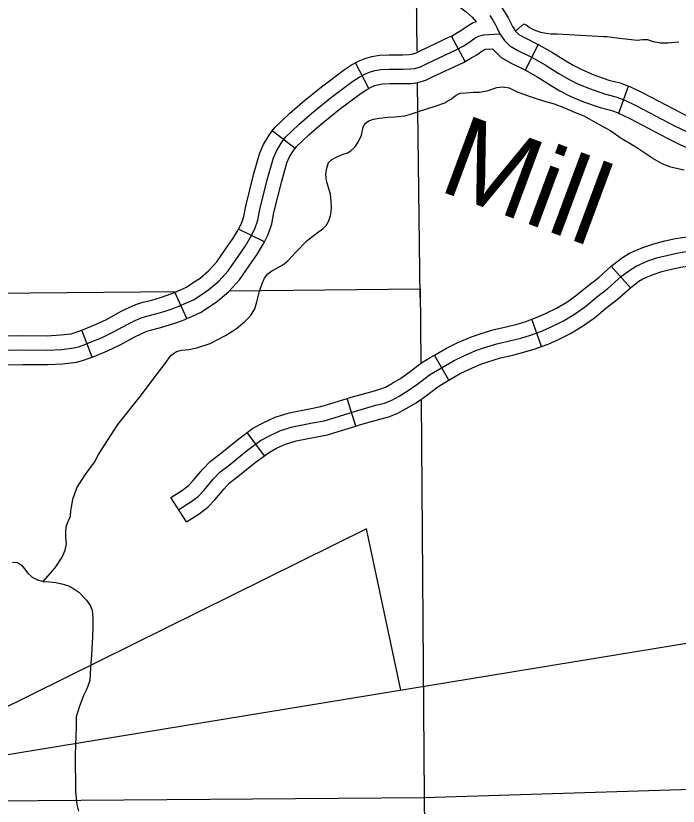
# Model space of a CAD drawing. Extents: x -3711 to 825, y -151 to 1050.
# Drawn here: x -2857.63 to -2819.08, y 378.25 to 424.26 of the extents above; entities that cross this region are included whole.
import ezdxf

# ---------------------------------------------------------------- set-up
doc = ezdxf.new("R2010")
doc.units = 0
for name, color, linetype in [('Level 32', 7, 'Continuous'), ('Level 35', 7, 'Continuous'), ('Level 46', 7, 'Continuous'), ('Level 5', 7, 'Continuous'), ('Level 8', 7, 'Continuous'), ('R_Dimension', 7, 'Continuous')]:
    doc.layers.add(name, color=color, linetype=linetype)

msp = doc.modelspace()

# ---------------------------------------------------------------- linework, layer by layer
at = {"layer": 'Level 32'}
for p, q in [((-2831.468, 421.611), (-2832.277, 423.084)), ((-2827.96, 421.091), (-2827.223, 422.602)), ((-2837.085, 420.034), (-2837.858, 421.527)), ((-2822.533, 418.595), (-2821.959, 420.175)), ((-2841.374, 416.53), (-2842.704, 417.558)), ((-2843.153, 411.098), (-2844.657, 411.85)), ((-2821.857, 408.431), (-2822.976, 409.685)), ((-2847.678, 406.635), (-2848.365, 408.17)), ((-2827.023, 405.018), (-2827.598, 406.598)), ((-2853.182, 404.399), (-2853.791, 405.965)), ((-2832.418, 403.056), (-2833.264, 404.509)), ((-2837.835, 400.379), (-2838.334, 401.984)), ((-2843.154, 398.657), (-2844.158, 400.006)), ((-2847.691, 394.81), (-2848.594, 396.228))]:
    msp.add_line(p, q, dxfattribs=at)
for points in [[(-2831.581, 426.503), (-2831.428, 426.451), (-2830.858, 426.182), (-2830.328, 425.784), (-2829.868, 425.355), (-2829.37, 424.794), (-2829.145, 424.433), (-2828.98, 424.149), (-2828.881, 423.958), (-2828.72, 423.633), (-2828.54, 423.369), (-2828.351, 423.18), (-2828.02, 422.991), (-2827.223, 422.602)], [(-2832.128, 424.913), (-2832.061, 424.891), (-2831.729, 424.734), (-2831.409, 424.494), (-2831.073, 424.18), (-2830.837, 423.914)], [(-2830.046, 424.289), (-2829.865, 424), (-2829.717, 423.744), (-2829.631, 423.578), (-2829.448, 423.208), (-2829.19, 422.83), (-2828.866, 422.507), (-2828.413, 422.247), (-2827.572, 421.837), (-2826.817, 421.405), (-2826.061, 420.93), (-2825.565, 420.628), (-2825.004, 420.347), (-2824.292, 420.045), (-2823.365, 419.721), (-2822.696, 419.548), (-2822.221, 419.376), (-2821.509, 419.03), (-2819.287, 417.864), (-2818.596, 417.519)], [(-2832.277, 423.084), (-2832.007, 423.232), (-2831.716, 423.403), (-2831.363, 423.662), (-2831.003, 423.871), (-2830.837, 423.914)], [(-2859.541, 404.788), (-2857.224, 404.812), (-2855.785, 404.8), (-2854.955, 404.847), (-2854.253, 404.929), (-2853.984, 404.999), (-2853.656, 405.116), (-2853.235, 405.28), (-2852.638, 405.526), (-2851.972, 405.842), (-2851.071, 406.333), (-2850.673, 406.521), (-2850.334, 406.673), (-2850.006, 406.778), (-2849.48, 406.907), (-2848.942, 407.071), (-2848.532, 407.212), (-2848.134, 407.352), (-2847.69, 407.551), (-2847.292, 407.738), (-2846.777, 408.066), (-2846.391, 408.324), (-2845.818, 408.815), (-2845.268, 409.412), (-2844.73, 410.197), (-2844.262, 410.864), (-2843.958, 411.368), (-2843.712, 411.859), (-2843.549, 412.374), (-2843.42, 413.007), (-2842.964, 414.856), (-2842.636, 415.992), (-2842.461, 416.39), (-2842.191, 416.847), (-2841.911, 417.21), (-2841.56, 417.549), (-2841.139, 417.947), (-2840.402, 418.591), (-2839.325, 419.469), (-2838.003, 420.452), (-2837.652, 420.687), (-2837.313, 420.862), (-2837.032, 420.991), (-2836.728, 421.073), (-2836.377, 421.131), (-2835.886, 421.155), (-2835.09, 421.155), (-2834.658, 421.167), (-2834.4, 421.202), (-2834.073, 421.295), (-2833.733, 421.459), (-2831.955, 422.302), (-2831.592, 422.501), (-2831.253, 422.7), (-2830.902, 422.958), (-2830.68, 423.087), (-2830.411, 423.157), (-2829.448, 423.208)], [(-2837.858, 421.527), (-2837.682, 421.618), (-2837.319, 421.784), (-2836.907, 421.895), (-2836.467, 421.969), (-2835.906, 421.995), (-2835.102, 421.995), (-2834.726, 422.006), (-2834.573, 422.026), (-2834.373, 422.084), (-2834.096, 422.217), (-2832.338, 423.051), (-2832.277, 423.084)], [(-2827.223, 422.603), (-2827.179, 422.581), (-2826.384, 422.126), (-2825.619, 421.645), (-2825.158, 421.364), (-2824.652, 421.111), (-2823.989, 420.83), (-2823.12, 420.526), (-2822.446, 420.352), (-2821.959, 420.175)], [(-2831.468, 421.611), (-2831.178, 421.77), (-2830.791, 421.997), (-2830.442, 422.253), (-2830.357, 422.302), (-2830.281, 422.322), (-2829.891, 422.342)], [(-2829.891, 422.342), (-2829.381, 421.833), (-2828.806, 421.504), (-2827.96, 421.091)], [(-2842.704, 417.558), (-2842.539, 417.772), (-2842.141, 418.157), (-2841.704, 418.569), (-2840.944, 419.233), (-2839.842, 420.132), (-2838.488, 421.14), (-2838.08, 421.412), (-2837.858, 421.527)], [(-2837.085, 420.034), (-2836.944, 420.106), (-2836.746, 420.198), (-2836.549, 420.251), (-2836.288, 420.294), (-2835.866, 420.314), (-2835.079, 420.314), (-2834.589, 420.327), (-2834.227, 420.377), (-2833.772, 420.507), (-2833.37, 420.701), (-2831.573, 421.553), (-2831.468, 421.611)], [(-2827.965, 421.094), (-2827.249, 420.684), (-2826.504, 420.216), (-2825.973, 419.892), (-2825.357, 419.584), (-2824.595, 419.261), (-2823.609, 418.916), (-2822.945, 418.745), (-2822.533, 418.595)], [(-2821.958, 420.175), (-2821.893, 420.151), (-2821.13, 419.781), (-2818.903, 418.612), (-2818.244, 418.283), (-2817.725, 418.063), (-2817.187, 417.863), (-2816.65, 417.704)], [(-2841.374, 416.53), (-2841.283, 416.647), (-2840.979, 416.941), (-2840.573, 417.325), (-2839.859, 417.949), (-2838.808, 418.806), (-2837.519, 419.765), (-2837.225, 419.961), (-2837.085, 420.034)], [(-2822.549, 418.601), (-2821.888, 418.28), (-2819.67, 417.116), (-2818.949, 416.755), (-2818.345, 416.5), (-2817.719, 416.267), (-2817.128, 416.092)], [(-2844.657, 411.85), (-2844.494, 412.176), (-2844.363, 412.586), (-2844.24, 413.191), (-2843.776, 415.074), (-2843.428, 416.279), (-2843.21, 416.774), (-2842.889, 417.319), (-2842.704, 417.558)], [(-2843.153, 411.098), (-2842.931, 411.542), (-2842.734, 412.163), (-2842.6, 412.822), (-2842.151, 414.639), (-2841.844, 415.705), (-2841.711, 416.006), (-2841.494, 416.374), (-2841.374, 416.53)], [(-2848.365, 408.17), (-2848.041, 408.315), (-2847.699, 408.476), (-2847.236, 408.77), (-2846.9, 408.995), (-2846.403, 409.421), (-2845.927, 409.938), (-2845.421, 410.676), (-2844.967, 411.323), (-2844.695, 411.773), (-2844.657, 411.85)], [(-2822.976, 409.685), (-2822.907, 409.747), (-2822.31, 410.201), (-2821.903, 410.445), (-2821.135, 410.782), (-2820.491, 410.996), (-2819.851, 411.157), (-2819.233, 411.294), (-2818.416, 411.414), (-2817.906, 411.414), (-2817.393, 411.414), (-2816.907, 411.414), (-2816.766, 411.402)], [(-2847.678, 406.635), (-2847.339, 406.787), (-2846.886, 407.001), (-2846.318, 407.362), (-2845.883, 407.653), (-2845.233, 408.21), (-2844.609, 408.887), (-2844.039, 409.718), (-2843.557, 410.405), (-2843.221, 410.962), (-2843.153, 411.098)], [(-2848.142, 395.519), (-2847.437, 395.968), (-2847.01, 396.289), (-2846.668, 396.652), (-2846.134, 397.294), (-2845.749, 397.7), (-2845.215, 398.107), (-2844.211, 398.919), (-2843.377, 399.539), (-2842.822, 399.839), (-2842.223, 400.117), (-2841.518, 400.33), (-2840.364, 400.566), (-2839.68, 400.694), (-2839.103, 400.865), (-2837.864, 401.25), (-2836.667, 401.592), (-2836.176, 401.72), (-2835.748, 401.892), (-2835.321, 402.127), (-2834.787, 402.448), (-2834.231, 402.832), (-2833.547, 403.367), (-2833.077, 403.645), (-2832.159, 404.18), (-2831.582, 404.458), (-2830.855, 404.778), (-2830.406, 404.928), (-2829.637, 405.163), (-2828.889, 405.334), (-2828.227, 405.506), (-2827.671, 405.677), (-2826.966, 405.933), (-2826.432, 406.168), (-2825.748, 406.511), (-2825.107, 406.896), (-2824.466, 407.345), (-2823.825, 407.879), (-2823.162, 408.392), (-2822.372, 409.098), (-2821.837, 409.504), (-2821.517, 409.697), (-2820.833, 409.996), (-2820.256, 410.189), (-2819.658, 410.338), (-2819.081, 410.467), (-2818.354, 410.574)], [(-2827.598, 406.598), (-2827.279, 406.714), (-2826.789, 406.929), (-2826.153, 407.248), (-2825.565, 407.601), (-2824.977, 408.013), (-2824.351, 408.534), (-2823.7, 409.039), (-2822.976, 409.685)], [(-2821.857, 408.431), (-2821.836, 408.449), (-2821.365, 408.807), (-2821.13, 408.948), (-2820.531, 409.211), (-2820.021, 409.381), (-2819.465, 409.52), (-2818.928, 409.64), (-2818.293, 409.733), (-2817.906, 409.733), (-2817.393, 409.733), (-2816.98, 409.733), (-2816.912, 409.727)], [(-2853.791, 405.965), (-2853.548, 406.06), (-2852.979, 406.295), (-2852.353, 406.591), (-2851.452, 407.083), (-2851.024, 407.285), (-2850.635, 407.459), (-2850.235, 407.588), (-2849.702, 407.718), (-2849.201, 407.871), (-2848.809, 408.005), (-2848.447, 408.133), (-2848.365, 408.17)], [(-2827.023, 405.018), (-2826.652, 405.153), (-2826.074, 405.407), (-2825.343, 405.773), (-2824.649, 406.19), (-2823.955, 406.676), (-2823.298, 407.224), (-2822.624, 407.746), (-2821.857, 408.431)], [(-2853.182, 404.399), (-2852.922, 404.499), (-2852.298, 404.757), (-2851.59, 405.092), (-2850.69, 405.584), (-2850.322, 405.757), (-2850.032, 405.887), (-2849.777, 405.969), (-2849.257, 406.096), (-2848.683, 406.271), (-2848.256, 406.418), (-2847.822, 406.571), (-2847.678, 406.635)], [(-2833.264, 404.509), (-2832.553, 404.923), (-2831.934, 405.221), (-2831.158, 405.563), (-2830.662, 405.729), (-2829.854, 405.976), (-2829.088, 406.151), (-2828.456, 406.315), (-2827.939, 406.474), (-2827.598, 406.598)], [(-2859.272, 405.632), (-2857.225, 405.652), (-2855.806, 405.641), (-2855.027, 405.685), (-2854.408, 405.757), (-2854.232, 405.803), (-2853.95, 405.904), (-2853.791, 405.965)], [(-2832.418, 403.056), (-2831.764, 403.437), (-2831.229, 403.694), (-2830.552, 403.994), (-2830.15, 404.127), (-2829.42, 404.351), (-2828.69, 404.518), (-2827.998, 404.696), (-2827.403, 404.879), (-2827.023, 405.018)], [(-2838.334, 401.984), (-2838.104, 402.056), (-2836.889, 402.403), (-2836.439, 402.521), (-2836.109, 402.653), (-2835.74, 402.856), (-2835.243, 403.154), (-2834.73, 403.51), (-2834.022, 404.063), (-2833.503, 404.37), (-2833.264, 404.509)], [(-2859.348, 403.949), (-2857.223, 403.971), (-2855.765, 403.959), (-2854.882, 404.009), (-2854.097, 404.1), (-2853.736, 404.195), (-2853.362, 404.328), (-2853.182, 404.399)], [(-2837.835, 400.379), (-2837.624, 400.444), (-2836.446, 400.781), (-2835.912, 400.92), (-2835.388, 401.13), (-2834.902, 401.398), (-2834.331, 401.741), (-2833.733, 402.155), (-2833.073, 402.671), (-2832.652, 402.92), (-2832.418, 403.056)], [(-2844.158, 400.006), (-2843.83, 400.25), (-2843.198, 400.59), (-2842.524, 400.904), (-2841.724, 401.146), (-2840.526, 401.391), (-2839.878, 401.512), (-2839.348, 401.669), (-2838.334, 401.984)], [(-2843.154, 398.657), (-2842.924, 398.828), (-2842.445, 399.087), (-2841.923, 399.329), (-2841.312, 399.515), (-2840.203, 399.741), (-2839.483, 399.876), (-2838.859, 400.061), (-2837.835, 400.379)], [(-2848.594, 396.228), (-2847.916, 396.66), (-2847.572, 396.918), (-2847.298, 397.21), (-2846.763, 397.852), (-2846.312, 398.328), (-2845.734, 398.768), (-2844.726, 399.583), (-2844.158, 400.006)], [(-2847.691, 394.81), (-2846.958, 395.276), (-2846.447, 395.66), (-2846.038, 396.095), (-2845.505, 396.735), (-2845.186, 397.073), (-2844.696, 397.445), (-2843.695, 398.255), (-2843.154, 398.657)]]:
    msp.add_lwpolyline(points, dxfattribs=at)
at = {"layer": 'Level 35'}
for points in [[(-2832.325, 419.393), (-2831.994, 419.649), (-2831.767, 419.763), (-2831.439, 419.788), (-2831.009, 419.813), (-2830.643, 419.826), (-2830.201, 419.902), (-2829.621, 420.091), (-2829.28, 420.129), (-2828.913, 420.066), (-2828.408, 419.826), (-2827.638, 419.548), (-2826.805, 419.283), (-2826.3, 419.131), (-2825.694, 418.903), (-2825.062, 418.638), (-2824.57, 418.449), (-2823.812, 418.019), (-2822.991, 417.564), (-2822.385, 417.147)], [(-2840.662, 411.174), (-2840.001, 411.681), (-2839.764, 411.863), (-2839.568, 412.058), (-2839.4, 412.324), (-2839.313, 412.633), (-2839.275, 412.874), (-2839.262, 413.088), (-2839.275, 413.48), (-2839.313, 413.884), (-2839.452, 414.327), (-2839.553, 414.655), (-2839.591, 415.047), (-2839.527, 415.401), (-2839.426, 415.717), (-2839.262, 415.881), (-2838.972, 416.033), (-2838.568, 416.209), (-2838.328, 416.285), (-2838.126, 416.412), (-2837.899, 416.626), (-2837.709, 416.917), (-2837.507, 417.321), (-2837.406, 417.776), (-2837.267, 418.016), (-2837.078, 418.143), (-2836.813, 418.244), (-2836.472, 418.307), (-2835.979, 418.358), (-2835.575, 418.383), (-2834.994, 418.433), (-2834.704, 418.522), (-2834.123, 418.711), (-2833.214, 419.002), (-2832.658, 419.204), (-2832.431, 419.343), (-2832.325, 419.393)], [(-2822.385, 417.147), (-2821.59, 416.667), (-2820.428, 415.896), (-2820.037, 415.669), (-2819.519, 415.466), (-2818.724, 415.302)], [(-2850.301, 402.197), (-2849.571, 403.196), (-2848.924, 404.033), (-2848.605, 404.48), (-2848.265, 404.714), (-2847.989, 404.799), (-2847.564, 404.841), (-2847.097, 404.926), (-2846.311, 405.181), (-2845.418, 405.649), (-2844.781, 406.053), (-2844.313, 406.457), (-2843.973, 406.797), (-2843.718, 407.201), (-2843.591, 407.605), (-2843.442, 408.243), (-2843.293, 408.69), (-2843.145, 408.987), (-2842.954, 409.243), (-2842.72, 409.413), (-2842.401, 409.583), (-2842.082, 409.774), (-2841.785, 410.008), (-2841.353, 410.482), (-2840.662, 411.174)], [(-2856.03, 391.342), (-2855.328, 392.135), (-2854.925, 392.752), (-2854.755, 393.156), (-2854.67, 393.518), (-2854.712, 393.879), (-2854.712, 394.198), (-2854.691, 394.538), (-2854.585, 394.836), (-2854.436, 395.134), (-2854.415, 395.453), (-2854.372, 395.75), (-2854.309, 396.133), (-2854.075, 396.792), (-2853.586, 397.536), (-2853.055, 398.281), (-2852.821, 398.727), (-2851.683, 400.467), (-2850.301, 402.197)], [(-2857.819, 392.464), (-2857.531, 392.434), (-2857.303, 392.282), (-2857.122, 392.07), (-2856.924, 391.827), (-2856.682, 391.584), (-2856.364, 391.433), (-2856.03, 391.342), (-2855.666, 391.311), (-2855.287, 391.266), (-2854.878, 391.175), (-2854.56, 391.084), (-2854.363, 390.978), (-2853.953, 390.705), (-2853.514, 390.249), (-2853.302, 389.946), (-2853.18, 389.673), (-2853.15, 389.188), (-2853.15, 388.657), (-2853.165, 388.126), (-2853.211, 387.064), (-2853.271, 386.305), (-2853.317, 385.562), (-2853.484, 385.092), (-2853.681, 384.697), (-2853.938, 384.015), (-2854.12, 383.453), (-2854.12, 383.165), (-2854.12, 382.877), (-2854.166, 381.239), (-2854.151, 379.1), (-2854.075, 378.356), (-2853.969, 377.962)]]:
    msp.add_lwpolyline(points, dxfattribs=at)
at = {"layer": 'Level 46'}
for points in [[(-2823.396, 423.032), (-2826.127, 423.186), (-2826.468, 423.186), (-2826.759, 423.229), (-2827.079, 423.288), (-2827.437, 423.418), (-2827.744, 423.579), (-2827.925, 423.709), (-2828.038, 423.782), (-2828.046, 423.785), (-2828.178, 423.695), (-2828.545, 423.374)], [(-2819.035, 422.729), (-2819.671, 422.676), (-2820.099, 422.676), (-2820.513, 422.755), (-2820.78, 422.844), (-2820.84, 422.857), (-2820.952, 422.868), (-2821.156, 422.861), (-2821.454, 422.821), (-2822.648, 422.952), (-2823.228, 423.032), (-2823.396, 423.032)]]:
    msp.add_lwpolyline(points, dxfattribs=at)
at = {"layer": 'Level 5'}
for points in [[(-2834.263, 422.196), (-2834.305, 425.534)], [(-2834.083, 407.863), (-2834.24, 420.331)], [(-2873.813, 378.458), (-2833.857, 378.77), (-2817.67, 379.261)]]:
    msp.add_lwpolyline(points, dxfattribs=at)
at = {"layer": 'Level 8'}
for points in [[(-2858.943, 408.114), (-2848.244, 408.224)], [(-2845.191, 408.256), (-2834.089, 408.37), (-2834.056, 404.064)], [(-2834.039, 401.88), (-2833.857, 378.77), (-2833.534, 349.903)]]:
    msp.add_lwpolyline(points, dxfattribs=at)
at = {"layer": 'R_Dimension'}
for p, q in [((-2478.38, 443.501), (-2866.636, 379.848)), ((-2837.209, 394.409), (-2866.636, 379.848)), ((-2835.211, 385), (-2837.209, 394.409))]:
    msp.add_line(p, q, dxfattribs=at)

# ---------------------------------------------------------------- texts
at = {"layer": 'Level 35'}
msp.add_text('Mill', height=4.7343, rotation=339.6228, dxfattribs=at).set_placement((-2833.119, 414.124))

doc.saveas('drawing.dxf')
